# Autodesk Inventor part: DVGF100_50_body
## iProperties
Created: 2010-04
Part Number: DVGF100_50_body
Document SubType Name: Modeling
Designer: TB
Mass: 2348.37 g
Surface Area: 2593.57 cm^2
Volume: 2348.37 cm^3
Density: 1 g/cm^3
Author: TB
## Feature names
1. Kropp [Revolution]
2. Chamfer
3. Extrusion2
4. Hole1
5. Revolution2
6. Hole2
7. Fillet1
8. Extrusion3
9. Hole3
